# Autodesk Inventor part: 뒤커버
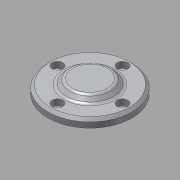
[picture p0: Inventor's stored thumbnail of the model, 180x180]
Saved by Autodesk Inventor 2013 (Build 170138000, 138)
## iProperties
Created: 2015-09
Part Number: 뒤커버
Material: 알루미늄 6061
Document SubType Name: Modeling
Designer: mduedu
Density: 1 g/cm^3
Author: mduedu
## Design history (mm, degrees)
sketch "스케치1"
  geometry: L1 (0, 7.5)-(0, -7.5); L2 (0, 7.5)-(14, 7.5); L3 (14, 7.5)-(18, 3.5); L4 (18, 3.5)-(31, 3.5); L5 (31, 3.5)-(31, -2.5); L6 (31, -2.5)-(17.5, -2.5); L7 (17.5, -2.5)-(17.5, -7.5); L8 (17.5, -7.5)-(0, -7.5); 2 further points
  constraints: 16 end point, 3 parallel, 2 perpendicular, 1 coincident, 1 horizontal, 1 midpoint, 1 vertical
  dimensions: "d0" = 15 distance of L1.start L1.end; "d1" = 4 distance between parallel lines of L4 L2; "d2" = 6 distance of L4.end L5.end; "d3" = 36 diameter of L3.end L1; "d4" = 35 diameter of L7 L1; "d5" = 62 diameter of L5 L1; "d7" = 45 deg angle of L3 L5
revolve "회전1" sketch "스케치1" stored, may be unused: angle "d8" = 90 deg
hole "구멍1" diameter "d11" = 24; stored, may be unused: countersink angle "d15" = 90 deg, drill point angle "d17" = 0 deg; dims "d9" = 10, "d10" = 10, "d12" = 6, "d13" = 4, "d14" = 2, "d16" = 8
fillet "모깎기1" dims "d18" = 3
chamfer "모따기1" distance "d19" = 1; stored, may be unused: second distance "d20" = 2, angle "d21" = 45 deg
chamfer "모따기2" distance "d22" = 2; stored, may be unused: second distance "d23" = 2, angle "d24" = 45 deg
fillet "모깎기2" dims "d25" = 3
fillet "모깎기3" dims "d26" = 3
sketch "스케치2" dims "d27" = 48
  geometry: 6 further points
  constraints: 2 vertical alignment, 1 coincident, 7 other
  dimensions: "d33" = 360 deg dimension on point (0, 0) point (0, 24) (derived)
sketch "스케치3"
  geometry: 4 further points
hole "구멍2" sketch "스케치3" at (-24, 0), (0, -24), (24, 0), (0, 24) diameter "d35" = 4.5; stored, may be unused: countersink angle "d39" = 90 deg, drill point angle "d41" = 0 deg; dims "d36" = 6, "d37" = 8, "d38" = 4.6, "d40" = 8
node "솔리드1"
